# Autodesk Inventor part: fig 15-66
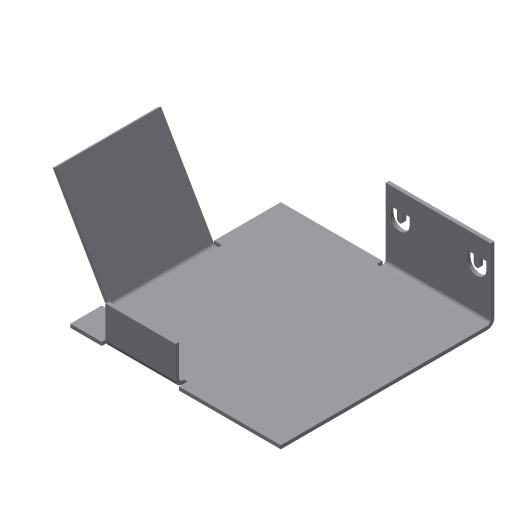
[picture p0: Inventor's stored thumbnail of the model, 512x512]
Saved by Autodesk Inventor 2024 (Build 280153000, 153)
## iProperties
Shininess: 77.0
Angle Display Precision: 2
Document Length Units: 11269
Document Angle Units: 11279
Document Time Units: 11290
Document Mass Units: 11283
Document Length Units Precision: 3
Document Angle Units Precision: 2
Created: 2002-04
Part Number: fig 15-66
Document SubType Name: Sheet Metal
Density: 1 g/cm^3
Sheet Metal Rule: Default
Material: Generic
Appearance: Default
Density: 0.0
Volumn: 0.0
Area: 0.0
PropertySet Name: Model Information
Control State: 0
Master: False
Checked Out: False
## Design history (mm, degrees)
node "Face1"
  sketch "Sketch1"
    geometry: L1 (12.647, 25.882)-(12.647, -14.118); L2 (12.647, -14.118)-(-17.353, -14.118); L3 (-17.353, -14.118)-(-17.353, 15.882); L4 (-17.353, 15.882)-(-2.353, 15.882); L5 (-2.353, 15.882)-(-2.353, 25.882); L6 (-2.353, 25.882)-(12.647, 25.882); 1 further point
    constraints: 12 end point, 4 parallel, 1 perpendicular
    dimensions: "d5" = 30 distance of L2.end L3.end; "d6" = 10 distance of L4.end L5.end; "d7" = 15 distance of L3.end L4.end; "d25" = 15 distance of L5.end L1.start
sketch "Sketch3"
  geometry: L1 (10, -15)-(10, 0)
  constraints: 2 end point
feature "Fold3" sketch "Sketch3" dims "d26" = 0.5 (= BendRadius), "d27" = 90 deg, "d28" = 0.5 (= BendRadius), "d96" = 0.5 (= BendReliefWidth), "d97" = 0.25 (= BendReliefDepth), "d98" = 1 (= MinimumRemnant), "d107" = 0.5 (= Thickness), "SeamGap" = 0.01
node "Flange2"
sketch "Sketch6"
  geometry: L1 (-6.914, 3.413)-(-5.843, 3.413); L2 (-5.843, 0.624)-(-6.914, 0.624); L3 (-6.914, 2.432)-(-5.843, 2.432); L4 (-5.843, 1.605)-(-6.914, 1.605); L5 (-6.914, 0.624)-(-6.914, 1.605); L6 (-6.914, 2.432)-(-6.914, 3.413); L7 (-6.914, 12.568)-(-6.914, 11.587); L8 (-6.914, 14.376)-(-6.914, 13.395); L9 (-6.914, 11.587)-(-5.843, 11.587); L10 (-5.843, 14.376)-(-6.914, 14.376); L11 (-6.914, 12.568)-(-5.843, 12.568); L12 (-5.843, 13.395)-(-6.914, 13.395); A1 r 1.394 centre (-5.843, 2.018) between (-5.843, 0.624) and (-5.843, 3.413); A2 r 0.413 centre (-5.843, 2.018) between (-5.843, 1.605) and (-5.843, 2.432); A3 r 1.394 centre (-5.843, 12.982) between (-5.843, 11.587) and (-5.843, 14.376); A4 r 0.413 centre (-5.843, 12.982) between (-5.843, 12.568) and (-5.843, 13.395)
  constraints: 24 end point, 8 point on circle, 4 centre point, 3 equal length, 1 perpendicular
cut "Cut1" sketch "Sketch6" dims "d49" = 0.5 (= Thickness), "d50" = 0
node "Flange3"
body "Solid1"
face "Plate1" dims "d107" = 0.5 (= Thickness)
sketch "Sketch5"
  geometry: L1 (20, 0)-(5, 0); L2 (5, 0)-(5, 15); L3 (5, 15)-(20, 15); L4 (20, 15)-(20, 0)
  constraints: 8 end point
face "Plate6" dims "d35" = 10, "d36" = 5, "d38" = 15, "d39" = 60 deg, "d40" = 0.5 (= BendRadius), "d107" = 0.5 (= Thickness), "MinimumRemnant" = 1 (= 2 x Thickness), "BendReliefWidth" = 0.5 (= Thickness)
bend "Bend5" dims "d38" = 15, "d39" = 60 deg, "d40" = 0.5 (= BendRadius), "d99" = 0.5 (= BendReliefWidth), "d100" = 0.25 (= BendReliefDepth), "d101" = 1 (= MinimumRemnant), "d107" = 0.5 (= Thickness), "SeamGap" = 0.01, "MinimumRemnant" = 1 (= 2 x Thickness), "BendReliefWidth" = 0.5 (= Thickness), "TransitionRadius" = 0.5 (= BendRadius)
sketch "Sketch7"
  geometry: L1 (25, 0)-(15, 0); L2 (15, 0)-(15, 5); L3 (15, 5)-(25, 5); L4 (25, 5)-(25, 0)
  constraints: 8 end point
face "Plate7" dims "d57" = 5, "d58" = 10, "d60" = 5, "d61" = 90 deg, "d62" = 0.5 (= BendRadius), "d107" = 0.5 (= Thickness), "MinimumRemnant" = 1 (= 2 x Thickness), "BendReliefWidth" = 0.5 (= Thickness)
bend "Bend7" dims "d59" = 0.5 (= BendRadius), "d60" = 5, "d61" = 90 deg, "d62" = 0.5 (= BendRadius), "d102" = 0.5 (= BendReliefWidth), "d103" = 0.25 (= BendReliefDepth), "d104" = 1 (= MinimumRemnant), "d107" = 0.5 (= Thickness), "SeamGap" = 0.01, "MinimumRemnant" = 1 (= 2 x Thickness), "BendReliefWidth" = 0.5 (= Thickness)
other parameters: "Thickness" = 0.5, "BendRadius" = 0.5 (= Thickness), "BendReliefDepth" = 0.25 (= 0.5 x Thickness), "CornerReliefSize" = 2 (= 4 x Thickness), "d0" = 0.5 (= BendRadius), "d13" = 0.5 (= BendRadius), "d31" = 0.5 (= BendRadius), "d37" = 0.5 (= BendRadius), "JacobiRadiusSize" = 0.5 (= Thickness), "GapSize" = 0.5 (= Thickness)
